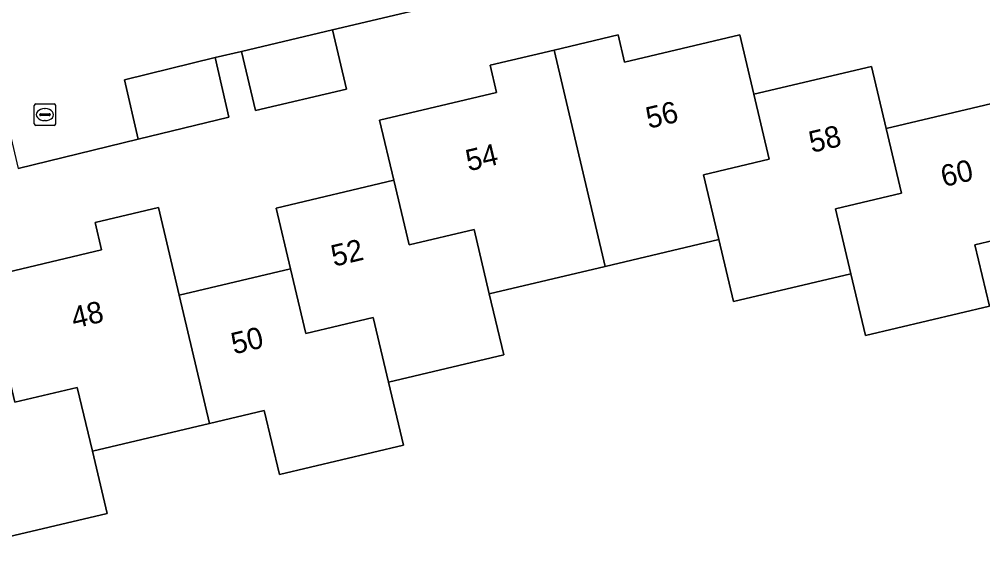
# Model space of a CAD drawing. Extents: x 158031 to 159244, y 380104 to 381214.
# Drawn here: x 158703.48 to 158748.37, y 380430.23 to 380454.8 of the extents above; entities that cross this region are included whole.
import ezdxf

# ---------------------------------------------------------------- set-up
doc = ezdxf.new("R2010")
doc.units = 0
for name, color, linetype in [('IMGEO_Erf', 7, 'Continuous'), ('IMGEO_Pand', 7, 'Continuous'), ('IMGEO_Pand_nummerreeks', 7, 'Continuous'), ('IMGEO_Rioolput', 7, 'Continuous'), ('IMGEO_Voetpad_open', 7, 'Continuous')]:
    doc.layers.add(name, color=color, linetype=linetype)

msp = doc.modelspace()

# ---------------------------------------------------------------- linework, layer by layer
at = {"layer": 'IMGEO_Erf'}
for points in [[(158751.736, 380462.236), (158746.999, 380461.102), (158747.606, 380458.522), (158743.352, 380457.522), (158742.746, 380460.102), (158741.538, 380459.818), (158742.145, 380457.239), (158737.92, 380456.246), (158737.314, 380458.825), (158732.106, 380457.601), (158732.16, 380457.367), (158723.351, 380455.296), (158723.296, 380455.53), (158718.08, 380454.306), (158718.734, 380451.552), (158714.495, 380450.547), (158713.842, 380453.301), (158712.603, 380453.018), (158713.245, 380450.248), (158709.015, 380449.219), (158703.434, 380447.849)], [(158701.892, 380442.78), (158707.32, 380444.067), (158707.019, 380445.336), (158709.967, 380446.035), (158710.934, 380441.953), (158716.12, 380443.182), (158715.451, 380446.005), (158720.932, 380447.304), (158720.268, 380450.104), (158725.715, 380451.395), (158725.415, 380452.66), (158728.398, 380453.367), (158731.382, 380454.074), (158731.684, 380452.799), (158737.055, 380454.072), (158737.71, 380451.307), (158743.187, 380452.605), (158743.872, 380449.717), (158749.319, 380451.008)], [(158750.754, 380444.95), (158748.003, 380444.298), (158748.681, 380441.436), (158742.908, 380440.068), (158742.225, 380442.949), (158736.76, 380441.654), (158736.076, 380444.542), (158730.78, 380443.287), (158725.382, 380442.008), (158726.053, 380439.177), (158720.687, 380437.905), (158721.385, 380434.963), (158715.603, 380433.593), (158714.896, 380436.577), (158712.343, 380435.972), (158706.887, 380434.679), (158707.572, 380431.787), (158702.164, 380430.506), (158702.795, 380427.844)]]:
    msp.add_lwpolyline(points, dxfattribs=at)
at = {"layer": 'IMGEO_Pand'}
for points in [[(158718.08, 380454.306), (158713.842, 380453.301), (158714.495, 380450.547), (158718.734, 380451.552)], [(158728.398, 380453.367), (158730.78, 380443.287), (158736.076, 380444.542), (158735.361, 380447.562), (158738.425, 380448.288), (158737.71, 380451.307), (158737.055, 380454.072), (158731.684, 380452.799), (158731.382, 380454.074)], [(158709.015, 380449.219), (158713.245, 380450.248), (158712.603, 380453.018), (158708.381, 380451.985)], [(158720.932, 380447.304), (158721.645, 380444.297), (158724.669, 380445.014), (158725.382, 380442.008), (158730.78, 380443.287), (158728.398, 380453.367), (158725.415, 380452.66), (158725.715, 380451.395), (158720.268, 380450.104)], [(158743.872, 380449.717), (158743.187, 380452.605), (158737.71, 380451.307), (158738.425, 380448.288), (158735.361, 380447.562), (158736.076, 380444.542), (158736.76, 380441.654), (158742.225, 380442.949), (158741.509, 380445.968), (158744.588, 380446.698)], [(158743.872, 380449.717), (158744.588, 380446.698), (158741.509, 380445.968), (158742.225, 380442.949), (158742.908, 380440.068), (158748.681, 380441.436), (158748.003, 380444.298), (158750.754, 380444.95), (158750.471, 380446.143), (158749.319, 380451.008)], [(158720.687, 380437.905), (158726.053, 380439.177), (158725.382, 380442.008), (158724.669, 380445.014), (158721.645, 380444.297), (158720.932, 380447.304), (158715.451, 380446.005), (158716.12, 380443.182), (158716.833, 380440.172), (158719.973, 380440.916)], [(158702.566, 380439.936), (158703.271, 380436.962), (158706.183, 380437.652), (158706.887, 380434.679), (158712.343, 380435.972), (158710.934, 380441.953), (158709.967, 380446.035), (158707.019, 380445.336), (158707.32, 380444.067), (158701.892, 380442.78)], [(158720.687, 380437.905), (158719.973, 380440.916), (158716.833, 380440.172), (158716.12, 380443.182), (158710.934, 380441.953), (158712.343, 380435.972), (158714.896, 380436.577), (158715.603, 380433.593), (158721.385, 380434.963)], [(158702.566, 380439.936), (158697.143, 380438.651), (158697.811, 380435.83), (158698.523, 380432.822), (158701.451, 380433.515), (158702.164, 380430.506), (158707.572, 380431.787), (158706.887, 380434.679), (158706.183, 380437.652), (158703.271, 380436.962)]]:
    msp.add_lwpolyline(points, close=True, dxfattribs=at)
at = {"layer": 'IMGEO_Rioolput'}
for p, q in [((158704.176, 380449.933), (158704.176, 380450.785)), ((158704.251, 380450.859), (158705.103, 380450.859)), ((158705.177, 380450.785), (158705.177, 380449.933)), ((158704.435, 380450.353), (158704.435, 380450.365)), ((158704.873, 380450.316), (158704.475, 380450.316)), ((158704.478, 380450.402), (158704.876, 380450.402)), ((158704.664, 380450.639), (158704.689, 380450.639)), ((158704.919, 380450.365), (158704.919, 380450.353)), ((158705.103, 380449.859), (158704.251, 380449.859)), ((158704.687, 380450.079), (158704.662, 380450.079))]:
    msp.add_line(p, q, dxfattribs=at)
for points in [[(158704.176, 380449.933), (158704.176, 380450.785)], [(158704.251, 380450.859), (158705.103, 380450.859)], [(158705.177, 380450.785), (158705.177, 380449.933)], [(158705.103, 380449.859), (158704.251, 380449.859)]]:
    msp.add_lwpolyline(points, dxfattribs=at)
for centre, radius, start, end in [((158704.253, 380450.783), 0.0765, 91.552, 178.448), ((158704.253, 380450.783), 0.0765, 91.552, 178.448), ((158705.101, 380450.783), 0.0765, 1.552, 88.448), ((158705.101, 380450.783), 0.0765, 1.552, 88.448), ((158704.475, 380450.362), 0.0403, 85.8775, 175.7526), ((158704.472, 380450.352), 0.0366, 178.938, 274.7102), ((158704.876, 380450.359), 0.043, 264.8664, 352.4533), ((158704.88, 380450.364), 0.0386, 1.7309, 96.639), ((158704.253, 380449.935), 0.0765, 181.552, 268.448), ((158704.253, 380449.935), 0.0765, 181.552, 268.448), ((158705.101, 380449.935), 0.0765, 271.552, 358.448), ((158705.101, 380449.935), 0.0765, 271.552, 358.448)]:
    msp.add_arc(centre, radius, start, end, dxfattribs=at)
for centre, major_axis, ratio, start_param, end_param in [((158704.663, 380450.359), (-0.387, 0.002), 0.722429, 4.712389, 7.853982), ((158704.688, 380450.359), (-0.39, 0.002), 0.717154, 1.570796, 4.712389)]:
    msp.add_ellipse(centre, major_axis=major_axis, ratio=ratio, start_param=start_param, end_param=end_param, dxfattribs=at)
at = {"layer": 'IMGEO_Voetpad_open'}
msp.add_lwpolyline([(158690.819, 380488.741), (158691.886, 380484.012), (158693.363, 380477.855), (158693.449, 380477.869), (158693.513, 380477.568), (158694.616, 380472.843), (158695.304, 380469.884), (158698.077, 380470.54), (158701.464, 380456.145), (158702.507, 380451.76), (158702.646, 380451.176), (158703.434, 380447.849), (158709.015, 380449.219), (158708.381, 380451.985), (158712.603, 380453.018), (158713.842, 380453.301), (158718.08, 380454.306), (158723.296, 380455.53), (158732.106, 380457.601), (158737.314, 380458.825), (158741.538, 380459.818), (158742.746, 380460.102), (158746.999, 380461.102), (158751.736, 380462.236)], dxfattribs=at)

# ---------------------------------------------------------------- texts
at = {"layer": 'IMGEO_Pand_nummerreeks'}
for s, rotation, p in [('56', 13.2991, (158732.808, 380449.698)), ('58', 13.3326, (158740.404, 380448.574)), ('54', 13.2991, (158724.415, 380447.714)), ('60', 13.3337, (158746.551, 380446.981)), ('52', 13.3331, (158718.141, 380443.272)), ('48', 13.3387, (158706.036, 380440.391)), ('50', 13.3322, (158713.483, 380439.186))]:
    msp.add_text(s, height=1, rotation=rotation, dxfattribs=at).set_placement(p)

doc.saveas('drawing.dxf')
